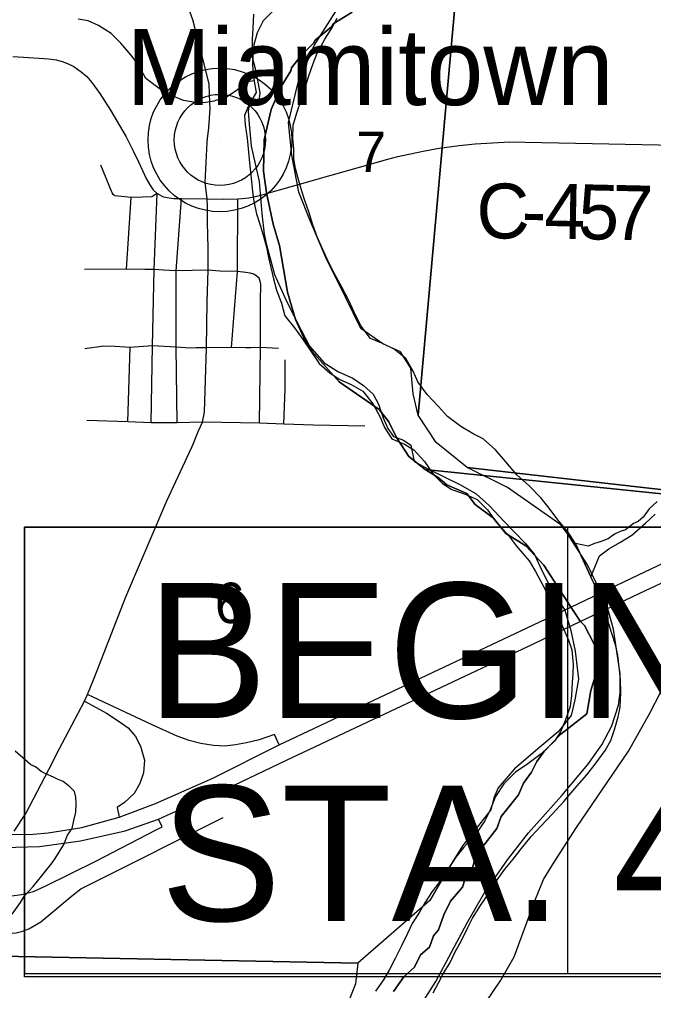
# Model space of a CAD drawing. Extents: x 0 to 34, y 0 to 22.
# Drawn here: x 3.978 to 4.634, y 16.77 to 17.776 of the extents above; entities that cross this region are included whole.
import ezdxf

# ---------------------------------------------------------------- set-up
doc = ezdxf.new("R2010")
doc.units = 0
for name, color, linetype in [('GM_X_County_Road', 7, 'Continuous'), ('GM_X_County_Road_Text', 7, 'Continuous'), ('GM_X_Interchange_Ramps', 7, 'Continuous'), ('GM_X_Interstate_Route', 7, 'Continuous'), ('GM_X_Major_River', 7, 'Continuous'), ('GM_X_Minor_River', 7, 'Continuous'), ('GM_X_Section', 7, 'Continuous'), ('GM_X_Section_Text', 7, 'Continuous'), ('GM_X_State_Route', 7, 'Continuous'), ('GM_X_Township_Road', 7, 'Continuous'), ('GM_X_Unincorporated', 7, 'Continuous'), ('GM_X_Unincorporated_Location', 7, 'Continuous'), ('GM_X_Unincorporated_Text', 7, 'Continuous'), ('GM_X_US_Route', 7, 'Continuous'), ('SH_Masking', 7, 'Continuous'), ('SH_Text', 7, 'Continuous')]:
    doc.layers.add(name, color=color, linetype=linetype)

msp = doc.modelspace()

# ---------------------------------------------------------------- linework, layer by layer
at = {"layer": 'GM_X_County_Road'}
for points in [[(3.9706, 17.7373), (3.9979, 17.7358), (4.0077, 17.7349), (4.0156, 17.7339), (4.022, 17.7322), (4.0274, 17.7301), (4.0339, 17.7269), (4.0415, 17.7217), (4.0473, 17.7166), (4.0527, 17.7106), (4.0608, 17.699), (4.0718, 17.6819), (4.088, 17.6543), (4.0953, 17.6399), (4.1012, 17.6275), (4.1088, 17.611), (4.1125, 17.6045), (4.1161, 17.5994), (4.1203, 17.5954), (4.1269, 17.5921), (4.1325, 17.5911), (4.1375, 17.5905), (4.1453, 17.5905), (4.172, 17.59)], [(4.3002, 17.6145), (4.3589, 17.6312), (4.3692, 17.6337), (4.3939, 17.639), (4.4099, 17.642), (4.4329, 17.6454), (4.4495, 17.6471), (4.4852, 17.6489), (4.5012, 17.6486), (4.5531, 17.6475), (4.639, 17.646), (4.6962, 17.6451), (4.725, 17.6448)], [(4.2326, 17.5953), (4.2335, 17.5956), (4.2578, 17.6024), (4.3002, 17.6145)], [(4.172, 17.59), (4.1887, 17.5898), (4.2036, 17.5899), (4.208, 17.5902), (4.2152, 17.5909), (4.2233, 17.5929), (4.2326, 17.5953)], [(4.4608, 16.7584), (4.4758, 16.7808), (4.4898, 16.8051), (4.5111, 16.863), (4.52, 16.8852), (4.5311, 16.9031), (4.5541, 16.939), (4.6079, 17.0181), (4.6302, 17.0574), (4.6415, 17.0795), (4.6592, 17.1193), (4.6746, 17.1506), (4.6868, 17.1744), (4.6941, 17.1903), (4.7027, 17.2129)]]:
    msp.add_lwpolyline(points, dxfattribs=at)
at = {"layer": 'GM_X_Interchange_Ramps'}
for points in [[(4.0448, 17.0697), (4.0493, 17.0674), (4.0676, 17.0573), (4.0807, 17.0487), (4.09, 17.0421), (4.0979, 17.0331), (4.1029, 17.023), (4.1069, 17.0086), (4.1061, 16.9956), (4.1022, 16.9845), (4.0965, 16.9742), (4.0865, 16.9647), (4.0788, 16.9597), (4.0807, 16.9496)], [(4.2466, 17.0247), (4.2418, 17.0351), (4.2257, 17.0298), (4.2128, 17.0266), (4.2012, 17.0246), (4.1901, 17.0232), (4.1785, 17.0239), (4.1653, 17.0259), (4.1533, 17.0292), (4.141, 17.0337), (4.1151, 17.0453), (4.054, 17.0738), (4.048, 17.0767)], [(3.9374, 16.8771), (3.9398, 16.8758), (3.9505, 16.8707), (3.9607, 16.8684), (3.9698, 16.8683), (3.9796, 16.8695), (3.9921, 16.8727), (4.0041, 16.8782), (4.0566, 16.9039), (4.1192, 16.9366), (4.1254, 16.9397), (4.1215, 16.9477)]]:
    msp.add_lwpolyline(points, dxfattribs=at)
at = {"layer": 'GM_X_Interstate_Route'}
msp.add_line((4.1215, 16.9477), (4.1305, 16.9517), dxfattribs=at)
for points in [[(2.8343, 17.6093), (3.4225, 17.2149), (3.5995, 17.097), (3.6679, 17.051), (3.741, 17.0021), (3.7789, 16.9786), (3.8063, 16.9653), (3.8379, 16.9533), (3.8686, 16.9439), (3.9015, 16.9368), (3.936, 16.9325), (3.9703, 16.9317), (3.9919, 16.9322), (4.0072, 16.9333), (4.0421, 16.9388), (4.0807, 16.9496), (4.1185, 16.9639), (4.1778, 16.99), (4.2466, 17.0247)], [(4.2466, 17.0247), (4.503, 17.1458), (4.5483, 17.1673), (4.6183, 17.2006), (4.7129, 17.2456), (4.7665, 17.2709), (4.8116, 17.292), (4.9272, 17.3464), (5.1142, 17.435)], [(4.1305, 16.9517), (4.1848, 16.9756), (4.2541, 17.0085), (4.5105, 17.1295), (4.5582, 17.1522), (4.6258, 17.1844), (4.7054, 17.2217), (4.8008, 17.2671), (4.8191, 17.2758), (4.9346, 17.3302), (5.1164, 17.4163)], [(3.5913, 17.0864), (3.6597, 17.0405), (3.7327, 16.9916), (3.7707, 16.9681), (3.7981, 16.9547), (3.8312, 16.9407), (3.8604, 16.9319), (3.8946, 16.9245), (3.9319, 16.9192), (3.9616, 16.9183), (3.9985, 16.9192), (4.0407, 16.9251), (4.0872, 16.9354), (4.1215, 16.9477)]]:
    msp.add_lwpolyline(points, dxfattribs=at)
at = {"layer": 'GM_X_Major_River'}
msp.add_line((4.5689, 17.1986), (4.5533, 17.2329), dxfattribs=at)
for points in [[(4.2424, 17.7869), (4.2298, 17.7744), (4.2238, 17.7621), (4.2203, 17.7496), (4.2192, 17.7386), (4.2189, 17.7284), (4.2204, 17.7139), (4.2226, 17.7002), (4.2154, 17.6882), (4.2105, 17.6762), (4.2113, 17.6667), (4.2132, 17.653), (4.2146, 17.6385), (4.2158, 17.6274), (4.2173, 17.6148), (4.219, 17.5977), (4.2202, 17.5874), (4.2229, 17.5744), (4.2267, 17.5629), (4.2301, 17.5514), (4.2332, 17.5399), (4.2355, 17.5292), (4.2378, 17.5188), (4.2405, 17.5073), (4.2436, 17.4955), (4.2488, 17.482), (4.2522, 17.469), (4.2625, 17.4565), (4.2712, 17.4441), (4.2785, 17.4332), (4.2879, 17.4196), (4.2994, 17.4094), (4.3094, 17.403), (4.321, 17.3977), (4.333, 17.3909), (4.3439, 17.3772), (4.3515, 17.3633), (4.3554, 17.3533), (4.363, 17.3413), (4.3761, 17.336), (4.3858, 17.33), (4.3968, 17.3179), (4.4059, 17.3047), (4.4154, 17.2953)], [(4.5259, 17.2698), (4.5175, 17.2799), (4.5054, 17.2929), (4.4924, 17.3043), (4.4811, 17.3175), (4.4704, 17.33), (4.4575, 17.3414), (4.4474, 17.3467), (4.4344, 17.3543), (4.4206, 17.3646), (4.4115, 17.3748), (4.3997, 17.3873), (4.3899, 17.4005), (4.3853, 17.4117), (4.3777, 17.4248), (4.3655, 17.4343), (4.3527, 17.4404), (4.3411, 17.4453), (4.3313, 17.4582), (4.3241, 17.4725), (4.3184, 17.4848), (4.3113, 17.4987), (4.3034, 17.513), (4.2962, 17.5277), (4.2898, 17.5412), (4.2859, 17.5508), (4.2814, 17.5631), (4.2772, 17.5765), (4.273, 17.5884), (4.2699, 17.598), (4.2662, 17.611), (4.2634, 17.6214), (4.2618, 17.6313), (4.2618, 17.6416), (4.2606, 17.653), (4.261, 17.6663), (4.2649, 17.6791), (4.2691, 17.6923), (4.2733, 17.7051), (4.2771, 17.7175), (4.2816, 17.7302), (4.2858, 17.7408), (4.2938, 17.7553), (4.301, 17.7669), (4.3066, 17.777)], [(4.4154, 17.2953), (4.4251, 17.2889), (4.439, 17.2843), (4.4514, 17.2786), (4.4621, 17.268), (4.4712, 17.2552), (4.4829, 17.2426), (4.492, 17.2302), (4.5052, 17.215), (4.5117, 17.2041), (4.5193, 17.1898), (4.5264, 17.1767), (4.5315, 17.167), (4.5357, 17.1574), (4.5399, 17.147), (4.546, 17.1328), (4.5494, 17.1228), (4.5509, 17.1079), (4.5506, 17.0985), (4.5499, 17.089), (4.5491, 17.0757), (4.5476, 17.0643), (4.5426, 17.0493), (4.5377, 17.0381), (4.5313, 17.0284), (4.5176, 17.0151), (4.504, 17.0049), (4.4912, 16.9962), (4.4791, 16.984), (4.4703, 16.971), (4.4641, 16.9556), (4.4593, 16.9459), (4.4497, 16.9317), (4.4375, 16.9184), (4.4292, 16.9081), (4.4193, 16.8928), (4.4129, 16.8831), (4.405, 16.8727), (4.3974, 16.8608), (4.3918, 16.8511), (4.3842, 16.8395), (4.3793, 16.8291), (4.3732, 16.8163), (4.3667, 16.8032), (4.3607, 16.792), (4.3543, 16.7812), (4.3463, 16.7693)], [(4.5533, 17.2329), (4.5453, 17.2453), (4.535, 17.2577), (4.5259, 17.2698)], [(4.4059, 16.7678), (4.4115, 16.7779), (4.4164, 16.788), (4.4232, 16.7985), (4.4288, 16.8101), (4.4353, 16.822), (4.4418, 16.8355), (4.4466, 16.8452), (4.455, 16.8583), (4.4638, 16.8713), (4.473, 16.8862), (4.4801, 16.8959), (4.4888, 16.9062), (4.4971, 16.917), (4.5074, 16.9296), (4.5176, 16.9407), (4.529, 16.9528), (4.5412, 16.9658), (4.5526, 16.9795), (4.5648, 16.9935), (4.5735, 17.0047), (4.5838, 17.0188), (4.5898, 17.0292), (4.594, 17.0416), (4.5974, 17.0537), (4.5993, 17.0635), (4.6001, 17.0787), (4.5998, 17.092), (4.5989, 17.1023), (4.5971, 17.1172), (4.5948, 17.1271), (4.5903, 17.1409), (4.5865, 17.1532), (4.5834, 17.1632), (4.5799, 17.1739), (4.576, 17.1843), (4.5689, 17.1986)]]:
    msp.add_lwpolyline(points, dxfattribs=at)
at = {"layer": 'GM_X_Minor_River'}
msp.add_line((4.5533, 17.2329), (4.5689, 17.1986), dxfattribs=at)
for points in [[(4.2206, 17.7123), (4.2132, 17.7113), (4.2034, 17.7029), (4.1926, 17.6956), (4.1788, 17.691), (4.1685, 17.6894), (4.1579, 17.6901), (4.1473, 17.6919), (4.1327, 17.698), (4.1222, 17.7044), (4.1085, 17.7147), (4.1005, 17.729), (4.0928, 17.7391), (4.0825, 17.7512), (4.0726, 17.7613), (4.0595, 17.7697), (4.0487, 17.7745), (4.0384, 17.776)], [(4.6377, 17.2766), (4.6295, 17.2689), (4.6231, 17.2603), (4.618, 17.256), (4.6134, 17.2538), (4.6048, 17.2473), (4.5994, 17.2456), (4.5936, 17.2427), (4.587, 17.238), (4.5786, 17.2349), (4.5728, 17.2332), (4.5663, 17.2304), (4.5533, 17.2329)], [(4.5689, 17.1986), (4.5779, 17.2203), (4.5876, 17.2276), (4.5992, 17.2341), (4.6116, 17.2417), (4.6257, 17.2542), (4.6358, 17.2634)], [(3.97, 16.8493), (3.9787, 16.8612), (3.9828, 16.8682), (3.9918, 16.8778), (4.0009, 16.8889), (4.0045, 16.8937), (4.0105, 16.9011), (4.014, 16.9059), (4.0189, 16.9133), (4.0237, 16.9215), (4.0274, 16.9309), (4.0322, 16.938), (4.034, 16.9463), (4.0359, 16.9549), (4.0365, 16.9633), (4.036, 16.9705), (4.0347, 16.9763), (4.0299, 16.981), (4.0229, 16.9865), (4.0177, 16.9886), (4.0128, 16.9911), (4.0049, 16.9944), (4.0001, 16.9968), (3.9942, 17.0016), (3.9893, 17.004), (3.9812, 17.0112), (3.9731, 17.0179)]]:
    msp.add_lwpolyline(points, dxfattribs=at)
at = {"layer": 'GM_X_Section'}
for points in [[(4.4341, 17.8543), (4.3904, 17.366), (4.3852, 17.3881), (4.3827, 17.4146), (4.3719, 17.4315), (4.3538, 17.44), (4.3309, 17.4556), (4.3152, 17.4882), (4.2947, 17.5292), (4.279, 17.5666), (4.2669, 17.5968), (4.2597, 17.6354), (4.2561, 17.6692), (4.2657, 17.709), (4.2826, 17.7488), (4.308, 17.7886), (4.3429, 17.8127), (4.3743, 17.8296), (4.4033, 17.8417)], [(3.9054, 16.8066), (4.328, 16.7986), (4.3256, 16.7771), (4.3103, 16.7385), (4.3, 16.7205), (4.2802, 16.7024), (4.2517, 16.6823), (4.2355, 16.6713), (4.2093, 16.6549), (4.1675, 16.6328), (4.1258, 16.6145), (4.0845, 16.5985), (4.0692, 16.5947), (4.0556, 16.5931), (4.0495, 16.5944), (4.0387, 16.6015), (4.0223, 16.614), (4.0029, 16.6235), (3.9905, 16.6288), (3.9622, 16.6321), (3.9299, 16.6291), (3.9079, 16.6163), (3.9011, 16.6124)]]:
    msp.add_lwpolyline(points, close=True, dxfattribs=at)
for points in [[(5.3785, 17.205), (4.4409, 17.3119), (4.4091, 17.3378), (4.3904, 17.366), (4.4341, 17.8543)], [(4.22, 17.7813), (4.2193, 17.7666), (4.2186, 17.7552), (4.2182, 17.7382), (4.2224, 17.7222), (4.2247, 17.7092), (4.2264, 17.6997), (4.2259, 17.6941), (4.225, 17.6918), (4.2224, 17.6915), (4.2189, 17.6904), (4.2155, 17.6875), (4.2142, 17.6807), (4.2154, 17.6674), (4.2175, 17.6446), (4.2257, 17.6081), (4.2286, 17.575), (4.2308, 17.5534), (4.2335, 17.5423), (4.2415, 17.5118), (4.2541, 17.4839), (4.2693, 17.454), (4.278, 17.4375), (4.2931, 17.42), (4.308, 17.411), (4.3226, 17.4042), (4.3338, 17.3967), (4.3438, 17.3877), (4.3492, 17.3774), (4.3542, 17.3632), (4.3589, 17.3521), (4.3647, 17.344), (4.3752, 17.34), (4.3827, 17.3349), (4.3861, 17.3181), (4.401, 17.3102), (4.434, 17.2939), (4.4504, 17.2844), (4.4638, 17.2723), (4.4796, 17.2556), (4.5011, 17.2335), (4.5106, 17.2215), (4.5186, 17.2043), (4.529, 17.184), (4.5422, 17.164), (4.5485, 17.143), (4.5529, 17.1216), (4.5564, 17.0924), (4.5525, 17.0713), (4.5486, 17.0551), (4.5354, 17.038), (4.5164, 17.0221), (4.4901, 16.9997), (4.473, 16.98), (4.4685, 16.9695), (4.4656, 16.9574), (4.4542, 16.9429), (4.4363, 16.9199), (4.4209, 16.8956), (4.4023, 16.8635), (4.328, 16.7986), (3.9054, 16.8066)], [(4.3854, 16.7431), (4.4086, 16.7793), (4.4411, 16.8402), (4.4582, 16.8701), (4.4829, 16.9055), (4.5044, 16.9334), (4.5391, 16.972), (4.566, 17.0043), (4.5805, 17.0247), (4.5908, 17.0442), (4.5978, 17.0656), (4.5996, 17.0785), (4.5993, 17.0982), (4.5925, 17.1445), (4.5852, 17.1701), (4.5657, 17.2111), (4.5445, 17.2438), (4.5379, 17.2523), (4.4828, 17.2912), (4.4409, 17.3119), (5.3785, 17.205), (5.2813, 16.2088)]]:
    msp.add_lwpolyline(points, dxfattribs=at)
at = {"layer": 'GM_X_State_Route'}
for points in [[(4.1748, 17.6895), (4.174, 17.7088), (4.1665, 17.7395), (4.1571, 17.7755), (4.1428, 17.8146), (4.1239, 17.8679), (4.1194, 17.8811)], [(4.3219, 17.7833), (4.3023, 17.7712), (4.3007, 17.7682), (4.2837, 17.7545), (4.2821, 17.7511), (4.2693, 17.7385), (4.2592, 17.7258), (4.2587, 17.7227), (4.2485, 17.7062), (4.2382, 17.6825), (4.231, 17.6511), (4.2303, 17.6188), (4.2333, 17.5961), (4.2402, 17.5639), (4.2469, 17.5417), (4.2552, 17.4934), (4.2635, 17.465), (4.2737, 17.4423), (4.2792, 17.4357), (4.2803, 17.4323), (4.3084, 17.4005), (4.35, 17.3719), (4.3599, 17.3592), (4.3679, 17.3427), (4.3808, 17.323), (4.3976, 17.3097), (4.72, 17.2764)], [(4.3648, 16.7691), (4.3756, 16.7843), (4.3866, 16.7942), (4.3927, 16.8069), (4.4021, 16.815), (4.4063, 16.8266), (4.4115, 16.833), (4.4169, 16.8486), (4.4239, 16.8628), (4.4364, 16.8773), (4.4387, 16.8847), (4.4467, 16.897), (4.4501, 16.9099), (4.4716, 16.9379), (4.4762, 16.9503), (4.4941, 16.9728), (4.4995, 16.9848), (4.5076, 16.9961), (4.5131, 17.0072), (4.5203, 17.0172), (4.538, 17.0356), (4.565, 17.0567), (4.5692, 17.0808), (4.5786, 17.1127), (4.5722, 17.1295), (4.5625, 17.1482), (4.558, 17.1528), (4.5521, 17.1615), (4.548, 17.1678), (4.5204, 17.2107), (4.5019, 17.2307), (4.4812, 17.2435), (4.4684, 17.2592), (4.4492, 17.2736), (4.4407, 17.2849), (4.42, 17.2937), (4.4111, 17.3015), (4.3976, 17.3097), (4.3808, 17.323), (4.3679, 17.3427), (4.3599, 17.3592), (4.35, 17.3719), (4.3084, 17.4005), (4.2803, 17.4323), (4.2792, 17.4357), (4.2737, 17.4423), (4.2635, 17.465), (4.2552, 17.4934), (4.2469, 17.5417), (4.2402, 17.5639), (4.2333, 17.5961), (4.2303, 17.6188), (4.231, 17.6511), (4.2382, 17.6825), (4.2485, 17.7062), (4.2587, 17.7227), (4.2592, 17.7258), (4.2693, 17.7385), (4.2821, 17.7511), (4.2837, 17.7545), (4.3007, 17.7682), (4.3023, 17.7712), (4.3219, 17.7833)], [(4.172, 17.6494), (4.1738, 17.6635), (4.175, 17.6835), (4.1748, 17.6895)], [(4.1724, 17.5653), (4.1722, 17.5816), (4.172, 17.59), (4.1698, 17.6069), (4.1719, 17.6484), (4.172, 17.6494)], [(4.1631, 17.3499), (4.1672, 17.3587), (4.1691, 17.3692), (4.1712, 17.4358), (4.1719, 17.4833), (4.1728, 17.5162), (4.1728, 17.5393), (4.1724, 17.5653)], [(4.0879, 17.178), (4.1303, 17.2771), (4.1559, 17.3327), (4.158, 17.3378), (4.1611, 17.3455), (4.1631, 17.3499)], [(4.72, 17.2764), (4.3976, 17.3097), (4.4111, 17.3015), (4.42, 17.2937), (4.4407, 17.2849), (4.4492, 17.2736), (4.4684, 17.2592), (4.4812, 17.2435), (4.5019, 17.2307), (4.5204, 17.2107), (4.548, 17.1678), (4.5521, 17.1615), (4.558, 17.1528), (4.5625, 17.1482), (4.5722, 17.1295), (4.5786, 17.1127), (4.5692, 17.0808), (4.565, 17.0567), (4.538, 17.0356), (4.5203, 17.0172), (4.5131, 17.0072), (4.5076, 16.9961), (4.4995, 16.9848), (4.4941, 16.9728), (4.4762, 16.9503), (4.4716, 16.9379), (4.4501, 16.9099), (4.4467, 16.897), (4.4387, 16.8847), (4.4364, 16.8773), (4.4239, 16.8628), (4.4169, 16.8486), (4.4115, 16.833), (4.4063, 16.8266), (4.4021, 16.815), (4.3927, 16.8069), (4.3866, 16.7942), (4.3756, 16.7843), (4.3648, 16.7691)], [(4.014, 17.0106), (4.0188, 17.0199), (4.0448, 17.0697), (4.048, 17.0767), (4.0548, 17.0935), (4.0852, 17.1716), (4.0879, 17.178)], [(3.9723, 16.935), (3.9843, 16.9535), (4.0117, 17.0063), (4.014, 17.0106)]]:
    msp.add_lwpolyline(points, dxfattribs=at)
at = {"layer": 'GM_X_Township_Road'}
for p, q in [((4.0884, 17.5172), (4.0931, 17.5914)), ((4.0898, 17.3592), (4.0923, 17.4362)), ((4.2525, 17.3951), (4.2525, 17.4232)), ((4.0898, 17.3592), (4.0475, 17.3606)), ((4.3351, 17.3546), (4.2821, 17.3556))]:
    msp.add_line(p, q, dxfattribs=at)
for points in [[(4.1203, 17.5954), (4.1148, 17.592), (4.1049, 17.5919), (4.0931, 17.5914), (4.0765, 17.5931), (4.0747, 17.5945), (4.0736, 17.5963), (4.0618, 17.625)], [(4.1138, 17.3582), (4.1153, 17.4379), (4.117, 17.5167), (4.1203, 17.5954)], [(4.141, 17.358), (4.14, 17.4365), (4.1399, 17.5155), (4.1453, 17.5905)], [(4.1971, 17.4359), (4.2033, 17.5148), (4.2036, 17.5899)], [(4.1075, 17.5169), (4.0884, 17.5172), (4.0451, 17.5167)], [(4.1728, 17.5162), (4.1399, 17.5155), (4.1268, 17.516), (4.117, 17.5167), (4.1075, 17.5169)], [(4.2257, 17.5078), (4.2228, 17.5103), (4.2201, 17.5119), (4.2165, 17.513), (4.212, 17.5138), (4.2033, 17.5148), (4.1851, 17.515), (4.1728, 17.5162)], [(4.2261, 17.3577), (4.2272, 17.436), (4.2272, 17.4881), (4.2276, 17.4974), (4.2275, 17.5017), (4.2267, 17.5049), (4.2257, 17.5078)], [(4.0762, 17.437), (4.0649, 17.4376), (4.0453, 17.4348)], [(4.1606, 17.4356), (4.1543, 17.4354), (4.14, 17.4365), (4.1153, 17.4379), (4.0923, 17.4362), (4.0762, 17.437)], [(4.2171, 17.4358), (4.2121, 17.4357), (4.1971, 17.4359), (4.1712, 17.4358), (4.1606, 17.4356)], [(4.2457, 17.4349), (4.2272, 17.436), (4.2171, 17.4358)], [(4.2512, 17.3568), (4.2525, 17.3932), (4.2525, 17.3951)], [(4.1672, 17.3587), (4.141, 17.358), (4.1138, 17.3582), (4.0898, 17.3592)], [(4.2821, 17.3556), (4.2512, 17.3568), (4.2261, 17.3577), (4.1672, 17.3587)], [(3.9271, 16.8633), (3.9501, 16.8407), (3.9604, 16.8329), (3.9658, 16.8304), (3.9706, 16.8295), (3.9743, 16.8299), (3.9798, 16.8311), (3.9875, 16.834), (3.9999, 16.8411), (4.0333, 16.8691), (4.0411, 16.8754), (4.0522, 16.8808), (4.1885, 16.9494)]]:
    msp.add_lwpolyline(points, dxfattribs=at)
at = {"layer": 'GM_X_Unincorporated'}
for radius in [0.0744, 0.0472]:
    msp.add_circle((4.1851, 17.651), radius, dxfattribs=at)
at = {"layer": 'GM_X_Unincorporated_Location'}
msp.add_line((4.1851, 17.651), (4.1851, 17.651), dxfattribs=at)
at = {"layer": 'GM_X_US_Route'}
msp.add_line((4.1215, 16.9477), (4.1305, 16.9517), dxfattribs=at)
for points in [[(4.1305, 16.9517), (4.1848, 16.9756), (4.2541, 17.0085), (4.5105, 17.1295), (4.5582, 17.1522), (4.6258, 17.1844), (4.7054, 17.2217), (4.8008, 17.2671), (4.8191, 17.2758), (4.9346, 17.3302), (5.1164, 17.4163)], [(3.5913, 17.0864), (3.6597, 17.0405), (3.7327, 16.9916), (3.7707, 16.9681), (3.7981, 16.9547), (3.8312, 16.9407), (3.8604, 16.9319), (3.8946, 16.9245), (3.9319, 16.9192), (3.9616, 16.9183), (3.9985, 16.9192), (4.0407, 16.9251), (4.0872, 16.9354), (4.1215, 16.9477)]]:
    msp.add_lwpolyline(points, dxfattribs=at)
at = {"layer": 'SH_Masking'}
for points in [[(3.9829, 16.7879), (5.0756, 16.7879), (5.0756, 17.2501), (3.9829, 17.2501)], [(4.545, 16.7879), (5.6377, 16.7879), (5.6377, 17.2501), (4.545, 17.2501)]]:
    msp.add_lwpolyline(points, close=True, dxfattribs=at)
at = {"layer": 'SH_Text'}
msp.add_lwpolyline([(3.9829, 17.2501), (5.6346, 17.2501), (5.6346, 16.7844), (3.9829, 16.7844)], close=True, dxfattribs=at)

# ---------------------------------------------------------------- texts
at = {"layer": 'GM_X_County_Road_Text'}
for s, rotation, p in [('C', 0.9914, (4.4512, 17.5485)), ('4', 358.9279, (4.5206, 17.5491)), ('5', 358.7145, (4.5556, 17.5484)), ('7', 358.6677, (4.5906, 17.5477)), ('-', 359.3755, (4.4974, 17.5494))]:
    msp.add_text(s, height=0.0568, rotation=rotation, dxfattribs=at).set_placement(p)
at = {"layer": 'GM_X_Section_Text'}
for s, p in [('7', (4.3261, 17.6178)), ('6', (4.1798, 17.1506))]:
    msp.add_text(s, height=0.0419, rotation=0, dxfattribs=at).set_placement(p)
at = {"layer": 'GM_X_Unincorporated_Text'}
msp.add_text('Miamitown', height=0.07898, rotation=0, dxfattribs=at).set_placement((4.0881, 17.6871))
at = {"layer": 'SH_Text'}
for s, p in [('BEGIN PROJECT', (4.1094, 17.0522)), ('STA. 444+50.00', (4.1237, 16.8422))]:
    msp.add_text(s, height=0.14, dxfattribs=at).set_placement(p)

doc.saveas('drawing.dxf')
